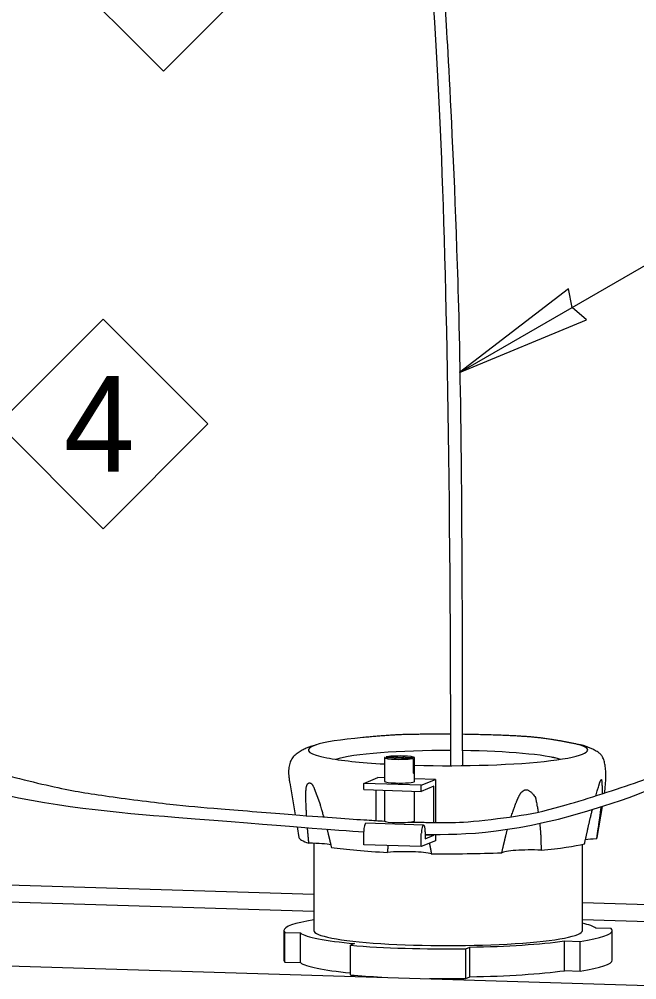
# Model space of a CAD drawing. Extents: x 99862 to 104211, y 98939 to 102076.
# Drawn here: x 102434.4 to 102537.9, y 100806.7 to 100967.5 of the extents above; entities that cross this region are included whole.
import ezdxf

# ---------------------------------------------------------------- set-up
doc = ezdxf.new("R2010")
doc.units = 0
for name, color, linetype in [('Level 1', 7, 'Continuous'), ('Level 15', 7, 'Continuous'), ('Level 20', 7, 'Continuous'), ('Level 30', 7, 'Continuous'), ('Level 4', 7, 'Continuous'), ('Level 5', 7, 'Continuous'), ('Level 8', 7, 'Continuous')]:
    doc.layers.add(name, color=color, linetype=linetype)

msp = doc.modelspace()

# ---------------------------------------------------------------- linework, layer by layer
at = {"layer": 'Level 1'}
for p, q in [((102483.78, 100820.93), (102372.64, 100824.31)), ((102366.26, 100821.73), (102483.78, 100818.15)), ((102653.5, 100815.76), (102528.78, 100819.56)), ((102528.78, 100816.78), (102653.5, 100812.99)), ((102653.26, 100802.22), (102325.35, 100812.21))]:
    msp.add_line(p, q, dxfattribs=at)
at = {"layer": 'Level 15'}
msp.add_line((102508.19, 100908.34), (102545.2, 100929.71), dxfattribs=at)
msp.add_lwpolyline([(102508.19, 100908.34), (102529.45, 100917.17), (102527.05, 100919.23), (102526.47, 100922.34)], close=True, dxfattribs=at)
at = {"layer": 'Level 20'}
for points in [[(102458.58, 100993.92), (102476.13, 100976.37), (102458.58, 100958.82), (102441.02, 100976.37)], [(102448.47, 100917.31), (102466.03, 100899.75), (102448.47, 100882.2), (102430.92, 100899.75)]]:
    msp.add_lwpolyline(points, close=True, dxfattribs=at)
at = {"layer": 'Level 30'}
for points in [[(102508.73, 100842.53), (102508.69, 100894.86), (102507.98, 100928.83), (102506.19, 100964.86), (102505.45, 100974.41), (102503.77, 100989.8), (102502.83, 100995.65), (102500.79, 101005.4), (102499.68, 101009.32), (102497.25, 101015.71), (102495.91, 101018.2), (102493.64, 101021.13), (102492.85, 101021.98), (102491.17, 101023.43), (102490.29, 101024.03), (102488.49, 101025.05), (102487.57, 101025.45), (102485.69, 101026.13), (102484.73, 101026.4), (102479.9, 101027.58), (102475.54, 101028.04), (102466.6, 101027.95), (102462.03, 101027.4), (102455.62, 101025.73), (102453.55, 101025.03), (102449.7, 101023.26), (102447.92, 101022.18), (102444.83, 101019.53), (102443.53, 101017.95), (102441.73, 101014.24), (102441.23, 101012.13), (102441.23, 101009.81)], [(102506.74, 100842.51), (102506.64, 100947.24), (102500.92, 101015.8), (102489.24, 101023.86), (102479.19, 101025.53), (102476.96, 101025.74)], [(102352.13, 100948.93), (102355.82, 100930.37), (102359.85, 100916.2), (102368.66, 100894.63), (102372.64, 100886.63), (102381.83, 100872.23), (102387.05, 100865.83), (102398.82, 100855.35), (102405.43, 100851.23), (102419.3, 100844.71), (102426.56, 100842.31), (102440.84, 100838.73), (102447.87, 100837.55), (102460.84, 100835.89), (102466.78, 100835.41), (102481.68, 100834.21), (102487.62, 100833.75), (102493.28, 100833.38), (102494.52, 100833.31), (102495.65, 100833.25)], [(102351.1, 100944.4), (102359.03, 100908.79), (102385.48, 100840.04), (102470.26, 100833.09), (102487.86, 100831.73), (102492.15, 100831.45)], [(102499.83, 100833.06), (102501.16, 100833.05), (102501.47, 100833.05), (102504.98, 100832.98), (102508.7, 100832.95), (102518.2, 100834.06), (102523.99, 100835.2), (102538.49, 100839.81), (102547.11, 100843.26), (102564.18, 100854.82), (102572.64, 100862.94), (102579.61, 100874.67)], [(102502.45, 100831.03), (102508.82, 100830.92), (102526.82, 100831.25), (102567.07, 100849.66), (102581.33, 100873.65)]]:
    msp.add_open_spline(points, degree=3, dxfattribs=at)
at = {"layer": 'Level 4'}
for p, q in [((102483.78, 100829.53), (102483.78, 100814.92)), ((102528.78, 100814.92), (102528.78, 100829.34)), ((102478.78, 100814.92), (102478.78, 100809.95)), ((102478.94, 100814.59), (102481.55, 100814.51)), ((102478.94, 100809.62), (102478.94, 100814.59)), ((102481.55, 100809.54), (102481.55, 100814.51)), ((102533.63, 100815.25), (102531.02, 100815.33)), ((102533.78, 100809.95), (102533.78, 100814.92)), ((102490.63, 100812.73), (102489.93, 100812.44)), ((102489.93, 100807.47), (102489.93, 100812.44)), ((102525.78, 100813.17), (102528.39, 100813.09)), ((102525.78, 100808.2), (102525.78, 100813.17)), ((102528.39, 100808.12), (102528.39, 100813.09)), ((102509.23, 100811.85), (102509.94, 100812.15)), ((102509.23, 100806.89), (102509.23, 100811.85)), ((102509.94, 100807.18), (102509.94, 100812.15)), ((102478.94, 100809.62), (102481.55, 100809.54)), ((102525.78, 100808.2), (102528.39, 100808.12)), ((102509.23, 100806.89), (102509.94, 100807.18))]:
    msp.add_line(p, q, dxfattribs=at)
for centre, major_axis, start_param, end_param in [((102506.28, 100814.92), (-27.5, 0), 5.670631, 6.283185), ((102506.28, 100814.92), (-25, 0), 3.288243, 3.592619), ((102506.28, 100814.92), (-27.5, 0), 0, 0.107302), ((102506.28, 100814.92), (-25, 0), 0.14665, 0.894413), ((102506.28, 100814.92), (-22.5, 0), 0, 3.141593), ((102506.28, 100814.92), (-27.5, 0), 2.504558, 3.141593), ((102506.28, 100814.92), (-27.5, 0), 3.141593, 3.248895), ((102506.28, 100814.92), (-27.5, 0), 0.933761, 1.678098), ((102506.28, 100814.92), (-25, 0), 1.717447, 2.465209), ((102506.28, 100809.95), (-27.5, 0), 0, 0.107302), ((102506.28, 100809.95), (-25, 0), 0.14665, 0.857545), ((102506.28, 100809.95), (-27.5, 0), 2.504558, 3.141593), ((102506.28, 100809.95), (-25, 0), 1.717447, 2.465209), ((102506.28, 100809.95), (-27.5, 0), 0.933761, 1.155187), ((102506.28, 100809.95), (-27.5, 0), 1.456673, 1.678098)]:
    msp.add_ellipse(centre, major_axis=major_axis, ratio=0.112235, start_param=start_param, end_param=end_param, dxfattribs=at)
at = {"layer": 'Level 5'}
for p, q in [((102483.79, 100845.86), (102483.68, 100845.82)), ((102479.76, 100839.63), (102480.65, 100834.3)), ((102483.86, 100838.71), (102484.73, 100836.36)), ((102531.28, 100830.51), (102532.15, 100835.7)), ((102480.99, 100832.27), (102481.29, 100830.51))]:
    msp.add_line(p, q, dxfattribs=at)
msp.add_lwpolyline([(102484.18, 100846), (102483.99, 100845.94), (102483.79, 100845.86)], dxfattribs=at)
for centre, major_axis, ratio, start_param, end_param in [((102506.28, 100845.14), (23.4, 0), 0.112235, 2.228403, 2.821263), ((102506.28, 100845.14), (23.4, 0), 0.112235, 2.923333, 3.662124), ((102506.28, 100845.14), (23.4, 0), 0.112235, 2.887509, 2.923333), ((102506.28, 100845.14), (23.4, 0), 0.112235, 2.867011, 2.887509), ((102506.28, 100845.14), (23.4, 0), 0.112235, 2.821263, 2.867011), ((102506.28, 100842.82), (-20, 0), 0.112235, 4.689966, 5.939235), ((102506.28, 100845.14), (23.4, 0), 0.112235, 4.469197, 6.607689), ((102506.28, 100842.82), (-20, 0), 0.112235, 3.485543, 4.589667), ((102506.28, 100845.14), (23.4, 0), 0.112235, 3.662124, 4.240627), ((102506.28, 100842.82), (-20, 0), 0.112235, 3.603731, 3.662124), ((102506.28, 100830.57), (-25, 0), 0.112235, 0.018826, 0.368061), ((102533.47, 100829.74), (-5.29, 0.02), 0.106412, 5.171338, 5.623147), ((102506.28, 100830.57), (-25, 0), 0.112235, 3.029196, 3.122767), ((102481.85, 100828.99), (5.24, 0.03), 0.108666, 0.418259, 1.356306), ((102506.28, 100830.57), (-25, 0), 0.112235, 0.673002, 1.15346), ((102506.28, 100830.57), (-25, 0), 0.112235, 2.243798, 2.724256), ((102498.91, 100827.52), (-5.02, -0.02), 0.11826, 3.56882, 5.293603), ((102506.28, 100830.57), (-25, 0), 0.112235, 1.4584, 1.938858), ((102520.29, 100827.82), (-5.08, 0.03), 0.11559, 4.398046, 6.122829)]:
    msp.add_ellipse(centre, major_axis=major_axis, ratio=ratio, start_param=start_param, end_param=end_param, dxfattribs=at)
for points in [[(102506.73, 100847.79), (102500.6, 100847.79), (102495.88, 100847.6), (102491.98, 100847.22)], [(102528.41, 100845.99), (102523.58, 100847.05), (102516.19, 100847.64), (102508.73, 100847.77)], [(102483.68, 100845.82), (102482.21, 100845.5), (102479.11, 100843.06), (102479.76, 100839.62)], [(102532.51, 100837.92), (102533.2, 100843.64), (102529.83, 100845.77), (102528.41, 100845.99)], [(102531.65, 100839.59), (102531.87, 100840.12), (102532.06, 100840.28), (102532.11, 100837.78)], [(102482.58, 100834.15), (102482.45, 100836.81), (102482.44, 100837.61), (102482.48, 100838.37)], [(102482.48, 100838.37), (102482.52, 100839.49), (102483.43, 100839.76), (102483.86, 100838.71)], [(102517.99, 100837.01), (102518.42, 100838.18), (102519.86, 100838.72), (102520.91, 100837.2)], [(102531.04, 100837.44), (102531.62, 100839.47), (102531.64, 100839.53), (102531.65, 100839.59)], [(102516.84, 100833.98), (102517.66, 100836.28), (102517.82, 100836.65), (102517.99, 100837.01)], [(102520.91, 100837.2), (102520.97, 100837), (102521.01, 100836.79), (102521.37, 100834.84)], [(102484.73, 100836.36), (102484.79, 100836.17), (102484.85, 100835.97), (102485.44, 100833.93)], [(102529.14, 100829.43), (102529.57, 100831.34), (102529.99, 100833.26), (102530.46, 100835.17)], [(102531.89, 100835.61), (102531.67, 100833.86), (102531.41, 100832.07), (102531.13, 100830.25)], [(102482.96, 100829.56), (102482.88, 100830.41), (102482.8, 100831.28), (102482.73, 100832.13)], [(102485.99, 100831.89), (102486.25, 100830.86), (102486.5, 100829.84), (102486.73, 100828.82)], [(102515.28, 100827.95), (102515.59, 100829.25), (102515.89, 100830.56), (102516.23, 100831.86)], [(102521.63, 100832.85), (102521.78, 100831.38), (102521.84, 100829.88), (102521.87, 100828.37)], [(102496.15, 100828), (102496.19, 100828.38), (102496.23, 100828.75), (102496.27, 100829.12)], [(102503.15, 100829.52), (102503.27, 100828.94), (102503.38, 100828.36), (102503.48, 100827.78)]]:
    msp.add_open_spline(points, degree=2, dxfattribs=at)
at = {"layer": 'Level 8'}
for p, q in [((102495.65, 100843.86), (102495.65, 100839.89)), ((102495.66, 100843.88), (102500.41, 100843.74)), ((102495.89, 100843.98), (102495.89, 100843.88)), ((102500.64, 100843.83), (102495.89, 100843.98)), ((102500.41, 100843.74), (102500.41, 100841.25)), ((102500.64, 100841.35), (102500.64, 100843.83)), ((102500.65, 100839.89), (102500.65, 100843.86)), ((102500.64, 100841.35), (102500.41, 100841.36)), ((102492.15, 100839.55), (102494.5, 100840.52)), ((102495.65, 100840.49), (102494.5, 100840.52)), ((102504.15, 100840.23), (102500.65, 100840.33)), ((102501.8, 100839.25), (102504.15, 100840.23)), ((102504.15, 100840.23), (102504.15, 100833.01)), ((102501.8, 100839.25), (102492.15, 100839.55)), ((102492.15, 100838.52), (102492.15, 100839.55)), ((102492.15, 100838.52), (102501.8, 100838.22)), ((102494.26, 100833.32), (102494.26, 100838.45)), ((102495.65, 100838.41), (102495.65, 100833.27)), ((102500.65, 100833.27), (102500.65, 100838.26)), ((102501.8, 100838.22), (102501.8, 100839.25)), ((102503.91, 100839.1), (102501.8, 100838.22)), ((102503.91, 100833.01), (102503.91, 100839.1)), ((102502.16, 100832.57), (102492.51, 100832.87)), ((102492.15, 100829.25), (102492.15, 100831.48)), ((102501.8, 100828.96), (102501.8, 100831.19)), ((102502.45, 100831.46), (102502.45, 100830.26)), ((102503.91, 100830.86), (102502.45, 100830.91)), ((102502.45, 100830.26), (102503.91, 100830.86)), ((102503.91, 100830.86), (102503.91, 100831.01)), ((102504.15, 100831.01), (102504.15, 100829.93)), ((102501.8, 100828.96), (102492.15, 100829.25)), ((102504.15, 100829.93), (102501.8, 100828.96))]:
    msp.add_line(p, q, dxfattribs=at)
for centre, major_axis, ratio, start_param, end_param in [((102498.15, 100843.86), (2.5, 0), 0.112235, 3.054033, 3.141593), ((102498.15, 100843.86), (2.5, 0), 0.112235, 3.141593, 5.841012), ((102498.15, 100843.86), (2.5, 0), 0.112235, 0, 2.699419), ((102498.15, 100843.86), (2.5, 0), 0.112235, 6.195626, 6.283185), ((102498.15, 100841.37), (2.5, 0), 0.112235, 5.841012, 6.195626), ((102498.15, 100839.89), (2.5, 0), 0.112235, 3.141593, 4.447522), ((102498.15, 100839.89), (2.5, 0), 0.112235, 4.447522, 6.283185), ((102492.47, 100831.62), (-0.04, -1.25), 0.260126, 3.141593, 4.828889), ((102498.15, 100833.27), (2.5, 0), 0.112235, 3.141593, 6.018319), ((102498.15, 100833.27), (2.5, 0), 0.112235, 6.018319, 6.283185), ((102502.13, 100831.33), (-0.04, -1.25), 0.260126, 3.141593, 4.828889), ((102502.13, 100831.33), (-0.04, -1.25), 0.260126, 1.687296, 3.141593)]:
    msp.add_ellipse(centre, major_axis=major_axis, ratio=ratio, start_param=start_param, end_param=end_param, dxfattribs=at)

# ---------------------------------------------------------------- texts
at = {"layer": 'Level 20'}
msp.add_text('4', height=16, dxfattribs=at).set_placement((102441.88, 100891.76))

doc.saveas('drawing.dxf')
